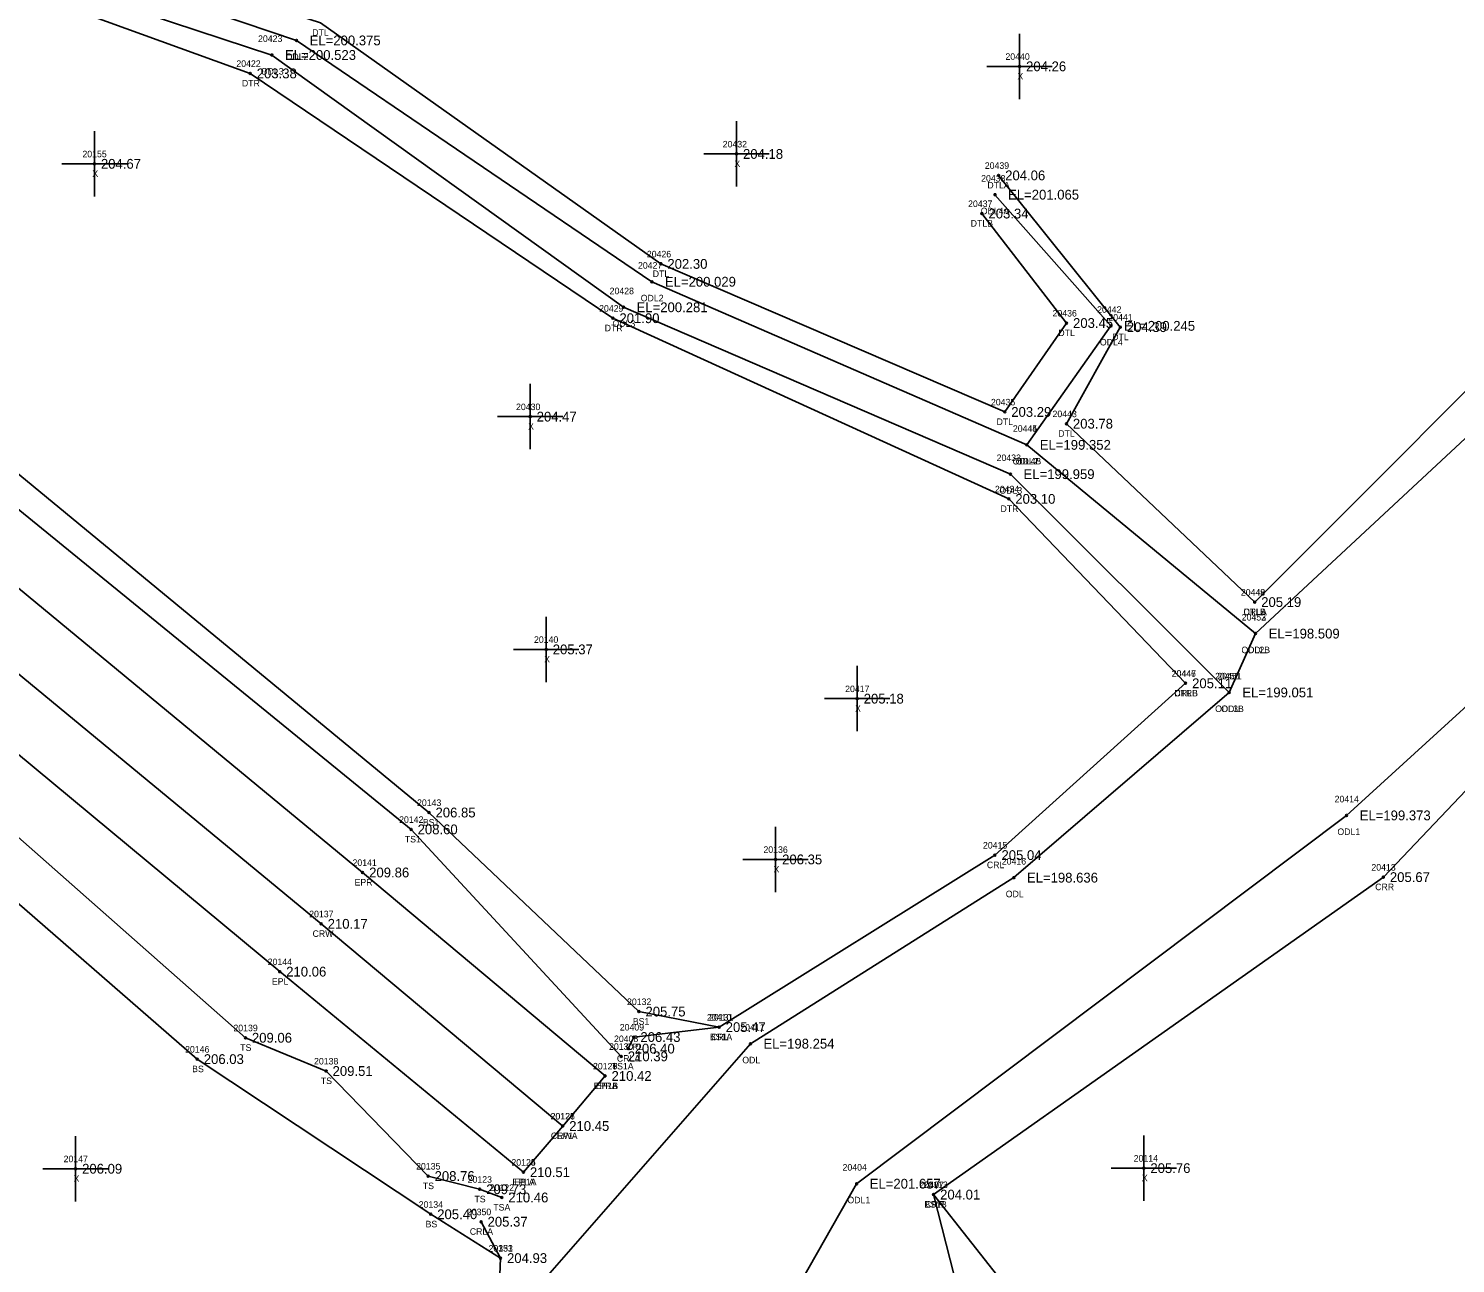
# Model space of a CAD drawing. Extents: x 2260230 to 2261304, y 1064626 to 1065587.
# Drawn here: x 2260697.7 to 2260916.2, y 1065083.4 to 1065272.4 of the extents above; entities that cross this region are included whole.
import ezdxf

# ---------------------------------------------------------------- set-up
doc = ezdxf.new("R2010")
doc.units = 0
for name, color, linetype in [('RD_DTM_BkLn1', 7, 'Continuous'), ('RD_DTM_BkLn2', 7, 'Continuous'), ('RD_DTM_BkLn_txCode', 7, 'Continuous'), ('RD_EX_H2O', 7, 'Continuous'), ('RD_EX_H2O_txCode', 7, 'Continuous'), ('RD_EX_Misc', 7, 'Continuous'), ('RD_EX_Misc_txCode', 7, 'Continuous'), ('RD_EX_Road', 7, 'Continuous'), ('RD_EX_Road_txCode', 7, 'Continuous'), ('RD_EX_TX_H2O_ELEV', 7, 'Continuous'), ('RD_EX_TX_Misc_ELEV', 7, 'Continuous'), ('RD_EX_TX_Road_ELEV', 7, 'Continuous'), ('RD_HC_Survey_ELEV', 7, 'Continuous'), ('RD_HC_Survey_txCode', 7, 'Continuous'), ('RD_SMD_Locator', 7, 'Continuous')]:
    doc.layers.add(name, color=color, linetype=linetype)

msp = doc.modelspace()

# ---------------------------------------------------------------- linework, layer by layer
at = {"layer": 'RD_DTM_BkLn1'}
msp.add_lwpolyline([(2260779.46, 1065104.44), (2260742.48, 1065135.39), (2260673.31, 1065192.46), (2260608.04, 1065246.07), (2260570.56, 1065278.04), (2260535.11, 1065309.57), (2260496.97, 1065343.67)], dxfattribs=at)
at = {"layer": 'RD_DTM_BkLn2'}
for points in [[(2260803.42, 1065119.58), (2260791.14, 1065121.96), (2260758.99, 1065152.43), (2260688.43, 1065210.53), (2260677.06, 1065221.37), (2260674.34, 1065224.52), (2260669.99, 1065225.64), (2260624.69, 1065267.1), (2260592.52, 1065295.67), (2260558.99, 1065321.26), (2260536.51, 1065353.04), (2260518.75, 1065355.5), (2260510.38, 1065360.52), (2260499.47, 1065369.14)], [(2260788.43, 1065115.1), (2260756.25, 1065149.85), (2260685.54, 1065207.45), (2260620.51, 1065261.6), (2260582.16, 1065294.05), (2260553.3, 1065320.76), (2260519.6, 1065347.28), (2260508.82, 1065355.88)], [(2260769.94, 1065084.22), (2260759.25, 1065090.93), (2260723.51, 1065114.68), (2260656.37, 1065173.06), (2260640.88, 1065186.75), (2260590.19, 1065225.63), (2260553.18, 1065256.82), (2260516.06, 1065288.21), (2260487.07, 1065314.86), (2260465.96, 1065334.21)], [(2260770.13, 1065093.5), (2260766.75, 1065094.76), (2260758.85, 1065096.78), (2260743.23, 1065112.86), (2260730.88, 1065117.95), (2260648.47, 1065190.67), (2260642.26, 1065193.52), (2260595.88, 1065231.39), (2260557.16, 1065261.19), (2260521.56, 1065295.46), (2260491.43, 1065319.65), (2260484.59, 1065329.16), (2260485.55, 1065330.24)], [(2260956, 1065026.37), (2260943.74, 1065012.58), (2260930.09, 1065011.21), (2260907.19, 1065027.84), (2260853.85, 1065071.62), (2260836.25, 1065093.94)]]:
    msp.add_lwpolyline(points, dxfattribs=at)
at = {"layer": 'RD_EX_H2O'}
for points in [[(2260649.32, 1065303.35), (2260742.36, 1065273.33), (2260794.49, 1065236.41), (2260847.14, 1065213.75), (2260856.6, 1065227.36), (2260843.65, 1065244.12)], [(2260648.37, 1065301.1), (2260738.72, 1065270.62), (2260793.11, 1065233.68), (2260850.51, 1065208.71), (2260885.55, 1065179.82)], [(2260646.91, 1065297.37), (2260734.94, 1065268.39), (2260788.77, 1065229.77), (2260848.02, 1065204.23), (2260881.52, 1065170.81)], [(2260646.56, 1065296.38), (2260731.62, 1065265.57), (2260787.15, 1065228.1), (2260847.76, 1065200.44), (2260874.83, 1065172.21)], [(2260885.41, 1065184.64), (2260936, 1065235.25), (2260958.14, 1065240.42), (2260996.14, 1065264.19), (2261041.44, 1065253.62), (2261057.19, 1065228.35), (2261051.93, 1065209.3), (2261057.29, 1065196.01), (2261078.07, 1065188.45), (2261181.25, 1065188.78), (2261285.07, 1065214.16)], [(2260772.5, 1065076.18), (2260808.2, 1065117.04), (2260848.54, 1065142.46), (2260881.52, 1065170.81), (2260885.55, 1065179.82), (2260940.26, 1065230.7), (2260962.59, 1065234.94), (2260997.55, 1065261.89), (2261039.02, 1065251.85), (2261039.02, 1065251.85), (2261052.94, 1065229.55), (2261043.13, 1065204.67), (2261054.65, 1065194.09), (2261077.36, 1065181.43), (2261181.44, 1065185.78), (2261286.2, 1065209.29)], [(2260846.21, 1065249.96), (2260864.84, 1065226.73), (2260856.58, 1065211.95), (2260885.41, 1065184.64)], [(2260845.65, 1065247.01), (2260863.41, 1065226.93), (2260850.51, 1065208.71)], [(2260798.69, 1065050.24), (2260824.47, 1065095.61), (2260899.49, 1065151.99), (2260934.71, 1065184.11), (2260972.92, 1065212.25), (2260990.72, 1065208.66), (2261010.85, 1065196.45), (2261038.36, 1065172.55), (2261071.49, 1065162.95), (2261185.1, 1065163.45), (2261291.17, 1065187.86)], [(2260835.04, 1065077.78), (2260839.45, 1065081.34), (2260836.25, 1065093.94), (2260905.11, 1065142.54), (2260939.15, 1065178.33), (2260943.42, 1065185.77), (2260976.49, 1065206.39), (2260992.26, 1065206.09), (2261009.06, 1065194.12), (2261027.03, 1065166.48), (2261074.3, 1065153.35), (2261181.18, 1065157.65), (2261291.85, 1065184.94)], [(2260789.48, 1065116.29), (2260790.36, 1065118.06), (2260803.42, 1065119.58), (2260845.64, 1065145.91), (2260874.83, 1065172.21)], [(2260766.96, 1065089.79), (2260769.94, 1065084.22), (2260769.59, 1065075.21), (2260766.59, 1065063.56), (2260718.2, 1065001.51), (2260666.03, 1064928.94), (2260617.31, 1064851.47), (2260573.34, 1064761.94), (2260536.11, 1064718.88), (2260488.15, 1064682.39)]]:
    msp.add_lwpolyline(points, dxfattribs=at)
at = {"layer": 'RD_EX_Misc'}
for p, q in [((2260849.41, 1065261.65), (2260849.41, 1065271.65)), ((2260844.41, 1065266.65), (2260854.41, 1065266.65)), ((2260806.07, 1065248.24), (2260806.07, 1065258.24)), ((2260707.76, 1065246.73), (2260707.76, 1065256.73)), ((2260801.07, 1065253.24), (2260811.07, 1065253.24)), ((2260702.76, 1065251.73), (2260712.76, 1065251.73)), ((2260774.48, 1065208.03), (2260774.48, 1065218.03)), ((2260769.48, 1065213.03), (2260779.48, 1065213.03)), ((2260776.94, 1065172.4), (2260776.94, 1065182.4)), ((2260771.94, 1065177.4), (2260781.94, 1065177.4)), ((2260824.55, 1065164.86), (2260824.55, 1065174.86)), ((2260819.55, 1065169.86), (2260829.55, 1065169.86)), ((2260812.06, 1065140.25), (2260812.06, 1065150.25)), ((2260807.06, 1065145.25), (2260817.06, 1065145.25)), ((2260704.88, 1065092.9), (2260704.88, 1065102.9)), ((2260868.44, 1065092.99), (2260868.44, 1065102.99)), ((2260699.88, 1065097.9), (2260709.88, 1065097.9)), ((2260863.44, 1065097.99), (2260873.44, 1065097.99))]:
    msp.add_line(p, q, dxfattribs=at)
at = {"layer": 'RD_EX_Road'}
for points in [[(2260785.94, 1065112.1), (2260748.83, 1065143.25), (2260679.89, 1065200.15), (2260614.93, 1065253.84), (2260576.4, 1065286.6), (2260541.88, 1065316.4), (2260503.82, 1065350.69)], [(2260773.44, 1065097.37), (2260736.13, 1065128.07), (2260602.8, 1065238.77), (2260563.77, 1065270.54), (2260528.16, 1065301.97), (2260490.72, 1065336.18)], [(2260773.44, 1065097.37), (2260779.46, 1065104.44), (2260785.94, 1065112.1)]]:
    msp.add_lwpolyline(points, dxfattribs=at)
at = {"layer": 'RD_SMD_Locator'}
for centre in [(2260738.72, 1065270.62), (2260734.94, 1065268.39), (2260849.41, 1065266.65), (2260731.62, 1065265.57), (2260806.07, 1065253.24), (2260707.76, 1065251.73), (2260846.21, 1065249.96), (2260845.65, 1065247.01), (2260843.65, 1065244.12), (2260794.49, 1065236.41), (2260793.11, 1065233.68), (2260788.77, 1065229.77), (2260787.15, 1065228.1), (2260856.6, 1065227.36), (2260863.41, 1065226.93), (2260864.84, 1065226.73), (2260847.14, 1065213.75), (2260774.48, 1065213.03), (2260856.58, 1065211.95), (2260850.51, 1065208.71), (2260850.51, 1065208.71), (2260848.02, 1065204.23), (2260847.76, 1065200.44), (2260885.41, 1065184.64), (2260885.41, 1065184.64), (2260885.55, 1065179.82), (2260885.55, 1065179.82), (2260776.94, 1065177.4), (2260874.83, 1065172.21), (2260874.83, 1065172.21), (2260881.52, 1065170.81), (2260881.52, 1065170.81), (2260824.55, 1065169.86), (2260758.99, 1065152.43), (2260899.49, 1065151.99), (2260756.25, 1065149.85), (2260812.06, 1065145.25), (2260845.64, 1065145.91), (2260748.83, 1065143.25), (2260848.54, 1065142.46), (2260905.11, 1065142.54), (2260742.48, 1065135.39), (2260736.13, 1065128.07), (2260791.14, 1065121.96), (2260730.88, 1065117.95), (2260790.36, 1065118.06), (2260803.42, 1065119.58), (2260803.42, 1065119.58), (2260789.48, 1065116.29), (2260808.2, 1065117.04), (2260723.51, 1065114.68), (2260788.43, 1065115.1), (2260743.23, 1065112.86), (2260785.94, 1065112.1), (2260785.94, 1065112.1), (2260779.46, 1065104.44), (2260779.46, 1065104.44), (2260868.44, 1065097.99), (2260704.88, 1065097.9), (2260758.85, 1065096.78), (2260773.44, 1065097.37), (2260773.44, 1065097.37), (2260766.75, 1065094.76), (2260824.47, 1065095.61), (2260836.25, 1065093.94), (2260836.25, 1065093.94), (2260770.13, 1065093.5), (2260759.25, 1065090.93), (2260766.96, 1065089.79), (2260769.94, 1065084.22), (2260769.94, 1065084.22)]:
    msp.add_circle(centre, 0.15, dxfattribs=at)

# ---------------------------------------------------------------- texts
at = {"layer": 'RD_DTM_BkLn_txCode'}
for s, p in [('20143', (2260757.16, 1065153.43)), ('20142', (2260754.42, 1065150.85)), ('BS1', (2260758.05, 1065150.43)), ('TS1', (2260755.29, 1065147.85)), ('20132', (2260789.31, 1065122.96)), ('20139', (2260729.05, 1065118.95)), ('BS1', (2260790.2, 1065119.96)), ('20131', (2260801.87, 1065120.58)), ('BS1A', (2260801.99, 1065117.58)), ('20146', (2260721.65, 1065115.68)), ('TS', (2260730.09, 1065115.95)), ('20130', (2260786.56, 1065116.1)), ('BS', (2260722.73, 1065112.68)), ('20138', (2260741.39, 1065113.86)), ('TS1A', (2260786.98, 1065113.1)), ('TS', (2260742.43, 1065110.86)), ('20135', (2260757.02, 1065097.78)), ('20123', (2260764.91, 1065095.76)), ('20113', (2260834.7, 1065094.94)), ('TS', (2260758.05, 1065094.78)), ('TS', (2260765.95, 1065092.76)), ('20122', (2260768.29, 1065094.5)), ('20134', (2260757.42, 1065091.93)), ('TSA', (2260768.84, 1065091.5)), ('BS1B', (2260834.84, 1065091.94)), ('BS', (2260758.47, 1065088.93)), ('20133', (2260768.11, 1065085.22))]:
    msp.add_text(s, height=1, dxfattribs=at).set_placement(p)
at = {"layer": 'RD_EX_H2O_txCode'}
for s, p in [('20423', (2260732.82, 1065270.39)), ('DTL', (2260741.12, 1065271.33)), ('ODL2', (2260737.03, 1065267.62)), ('20422', (2260729.5, 1065266.57)), ('ODL3', (2260733.24, 1065265.39)), ('DTR', (2260730.35, 1065263.57)), ('20439', (2260844.09, 1065250.96)), ('20438', (2260843.53, 1065249.01)), ('DTLA', (2260844.48, 1065247.96)), ('20437', (2260841.53, 1065245.12)), ('ODL4A', (2260843.47, 1065244.01)), ('DTLB', (2260841.93, 1065242.12)), ('20426', (2260792.35, 1065237.41)), ('20427', (2260790.99, 1065235.68)), ('DTL', (2260793.25, 1065234.41)), ('20428', (2260786.65, 1065231.77)), ('ODL2', (2260791.41, 1065230.68)), ('20429', (2260785.04, 1065229.1)), ('20436', (2260854.46, 1065228.36)), ('20442', (2260861.29, 1065228.93)), ('DTR', (2260785.89, 1065226.1)), ('ODL3', (2260787.08, 1065226.77)), ('20441', (2260863.01, 1065227.73)), ('DTL', (2260855.35, 1065225.36)), ('ODL4', (2260861.71, 1065223.93)), ('DTL', (2260863.6, 1065224.73)), ('20435', (2260845.03, 1065214.75)), ('20443', (2260854.46, 1065212.95)), ('DTL', (2260845.9, 1065211.75)), ('20444', (2260848.39, 1065210.71)), ('20445', (2260848.39, 1065210.71)), ('DTL', (2260855.34, 1065209.95)), ('20433', (2260845.9, 1065206.23)), ('ODL4B', (2260848.34, 1065205.71)), ('ODL2', (2260848.82, 1065205.71)), ('20434', (2260845.64, 1065201.44)), ('ODL3', (2260846.32, 1065201.23)), ('DTR', (2260846.49, 1065198.44)), ('20448', (2260883.3, 1065185.64)), ('20449', (2260883.3, 1065185.64)), ('CRLA', (2260883.7, 1065182.64)), ('DTLB', (2260883.7, 1065182.64)), ('20452', (2260883.43, 1065181.82)), ('20453', (2260883.43, 1065181.82)), ('ODL2B', (2260883.38, 1065176.82)), ('ODL', (2260884.3, 1065176.82)), ('20446', (2260872.69, 1065173.21)), ('20447', (2260872.72, 1065173.21)), ('20450', (2260879.36, 1065172.81)), ('20451', (2260879.69, 1065172.81)), ('CRLB', (2260873.13, 1065170.21)), ('DTRB', (2260873.09, 1065170.21)), ('ODL3B', (2260879.36, 1065167.81)), ('ODL', (2260880.28, 1065167.81)), ('20414', (2260897.65, 1065153.99)), ('ODL1', (2260898.08, 1065148.99)), ('20415', (2260843.81, 1065146.91)), ('CRL', (2260844.41, 1065143.91)), ('20416', (2260846.69, 1065144.46)), ('20413', (2260903.28, 1065143.54)), ('ODL', (2260847.3, 1065139.46)), ('CRR', (2260903.86, 1065140.54)), ('20409', (2260788.2, 1065119.06)), ('20410', (2260801.55, 1065120.58)), ('20411', (2260806.65, 1065119.04)), ('20408', (2260787.32, 1065117.29)), ('CRL', (2260802.19, 1065117.58)), ('CRL', (2260789.13, 1065116.06)), ('CRLA', (2260787.76, 1065114.29)), ('ODL', (2260806.96, 1065114.04)), ('20404', (2260822.31, 1065097.61)), ('20407', (2260834.1, 1065094.94)), ('20350', (2260764.8, 1065090.79)), ('ODL1', (2260823.06, 1065092.61)), ('CRR', (2260835, 1065091.94)), ('CRLA', (2260765.24, 1065087.79)), ('20351', (2260768.11, 1065085.22))]:
    msp.add_text(s, height=1, dxfattribs=at).set_placement(p)
at = {"layer": 'RD_EX_Misc_txCode'}
for s, p in [('20440', (2260847.25, 1065267.65)), ('X', (2260849.09, 1065264.65)), ('20155', (2260705.93, 1065252.73)), ('20432', (2260803.96, 1065254.24)), ('X', (2260805.76, 1065251.24)), ('X', (2260707.45, 1065249.73)), ('20430', (2260772.32, 1065214.03)), ('X', (2260774.17, 1065211.03)), ('20140', (2260775.07, 1065178.4)), ('X', (2260776.63, 1065175.4)), ('20417', (2260822.71, 1065170.86)), ('X', (2260824.23, 1065167.86)), ('20136', (2260810.2, 1065146.25)), ('X', (2260811.74, 1065143.25)), ('20147', (2260703.05, 1065098.9)), ('20114', (2260866.89, 1065098.99)), ('X', (2260704.57, 1065095.9)), ('X', (2260868.13, 1065095.99))]:
    msp.add_text(s, height=1, dxfattribs=at).set_placement(p)
at = {"layer": 'RD_EX_Road_txCode'}
for s, p in [('20141', (2260747.28, 1065144.25)), ('EPR', (2260747.6, 1065141.25)), ('20144', (2260734.3, 1065129.07)), ('EPL', (2260734.93, 1065126.07)), ('20128', (2260784.1, 1065113.1)), ('20129', (2260784.1, 1065113.1)), ('EPRA', (2260784.22, 1065110.1)), ('EP1B', (2260784.54, 1065110.1)), ('20126', (2260777.6, 1065105.44)), ('EP1', (2260778.54, 1065102.44)), ('20124', (2260771.61, 1065098.37)), ('20125', (2260771.61, 1065098.37)), ('EPLA', (2260771.75, 1065095.37)), ('EP1A', (2260772.03, 1065095.37))]:
    msp.add_text(s, height=1, dxfattribs=at).set_placement(p)
at = {"layer": 'RD_EX_TX_H2O_ELEV'}
for s, p in [('EL=200.375', (2260740.72, 1065269.87)), ('EL=200.523', (2260736.94, 1065267.64)), ('203.38', (2260732.62, 1065264.82)), ('204.06', (2260847.21, 1065249.21)), ('EL=201.065', (2260847.65, 1065246.26)), ('203.34', (2260844.65, 1065243.37)), ('202.30', (2260795.49, 1065235.66)), ('EL=200.029', (2260795.11, 1065232.93)), ('EL=200.281', (2260790.77, 1065229.02)), ('201.90', (2260788.15, 1065227.35)), ('203.45', (2260857.6, 1065226.61)), ('EL=200.245', (2260865.41, 1065226.18)), ('204.39', (2260865.84, 1065225.98)), ('203.29', (2260848.14, 1065213)), ('203.78', (2260857.58, 1065211.2)), ('EL=199.352', (2260852.51, 1065207.96)), ('EL=199.352', (2260852.51, 1065207.96)), ('EL=199.959', (2260850.02, 1065203.48)), ('203.10', (2260848.76, 1065199.69)), ('205.19', (2260886.41, 1065183.89)), ('205.19', (2260886.41, 1065183.89)), ('EL=198.509', (2260887.55, 1065179.07)), ('EL=198.509', (2260887.55, 1065179.07)), ('205.11', (2260875.83, 1065171.46)), ('205.11', (2260875.83, 1065171.46)), ('EL=199.051', (2260883.52, 1065170.06)), ('EL=199.051', (2260883.52, 1065170.06)), ('EL=199.373', (2260901.49, 1065151.24)), ('205.04', (2260846.64, 1065145.16)), ('EL=198.636', (2260850.54, 1065141.71)), ('205.67', (2260906.11, 1065141.79)), ('205.47', (2260804.42, 1065118.83)), ('206.43', (2260791.36, 1065117.31)), ('EL=198.254', (2260810.2, 1065116.29)), ('206.40', (2260790.48, 1065115.54)), ('EL=201.657', (2260826.47, 1065094.86)), ('204.01', (2260837.25, 1065093.19)), ('205.37', (2260767.96, 1065089.04)), ('204.93', (2260770.94, 1065083.47))]:
    msp.add_text(s, height=1.5, dxfattribs=at).set_placement(p)
at = {"layer": 'RD_EX_TX_Misc_ELEV'}
for s, p in [('204.26', (2260850.41, 1065265.9)), ('204.18', (2260807.07, 1065252.49)), ('204.67', (2260708.76, 1065250.98)), ('204.47', (2260775.48, 1065212.28)), ('205.37', (2260777.94, 1065176.65)), ('205.18', (2260825.55, 1065169.11)), ('206.85', (2260759.99, 1065151.68)), ('208.60', (2260757.25, 1065149.1)), ('206.35', (2260813.06, 1065144.5)), ('205.75', (2260792.14, 1065121.21)), ('205.47', (2260804.42, 1065118.83)), ('209.06', (2260731.88, 1065117.2)), ('210.39', (2260789.43, 1065114.35)), ('206.03', (2260724.51, 1065113.93)), ('209.51', (2260744.23, 1065112.11)), ('206.09', (2260705.88, 1065097.15)), ('205.76', (2260869.44, 1065097.24)), ('208.76', (2260759.85, 1065096.03)), ('209.73', (2260767.75, 1065094.01)), ('210.46', (2260771.13, 1065092.75)), ('204.01', (2260837.25, 1065093.19)), ('205.40', (2260760.25, 1065090.18)), ('204.93', (2260770.94, 1065083.47))]:
    msp.add_text(s, height=1.5, dxfattribs=at).set_placement(p)
at = {"layer": 'RD_EX_TX_Road_ELEV'}
for s, p in [('209.86', (2260749.83, 1065142.5)), ('210.06', (2260737.13, 1065127.32)), ('210.42', (2260786.94, 1065111.35)), ('210.42', (2260786.94, 1065111.35)), ('210.45', (2260780.46, 1065103.69)), ('210.51', (2260774.44, 1065096.62)), ('210.51', (2260774.44, 1065096.62))]:
    msp.add_text(s, height=1.5, dxfattribs=at).set_placement(p)
at = {"layer": 'RD_HC_Survey_ELEV'}
for s, p in [('210.17', (2260743.48, 1065134.64)), ('210.45', (2260780.46, 1065103.69))]:
    msp.add_text(s, height=1.5, dxfattribs=at).set_placement(p)
at = {"layer": 'RD_HC_Survey_txCode'}
for s, p in [('20137', (2260740.65, 1065136.39)), ('CRW', (2260741.17, 1065133.39)), ('20127', (2260777.62, 1065105.44)), ('CRWA', (2260777.65, 1065102.44))]:
    msp.add_text(s, height=1, dxfattribs=at).set_placement(p)

doc.saveas('drawing.dxf')
